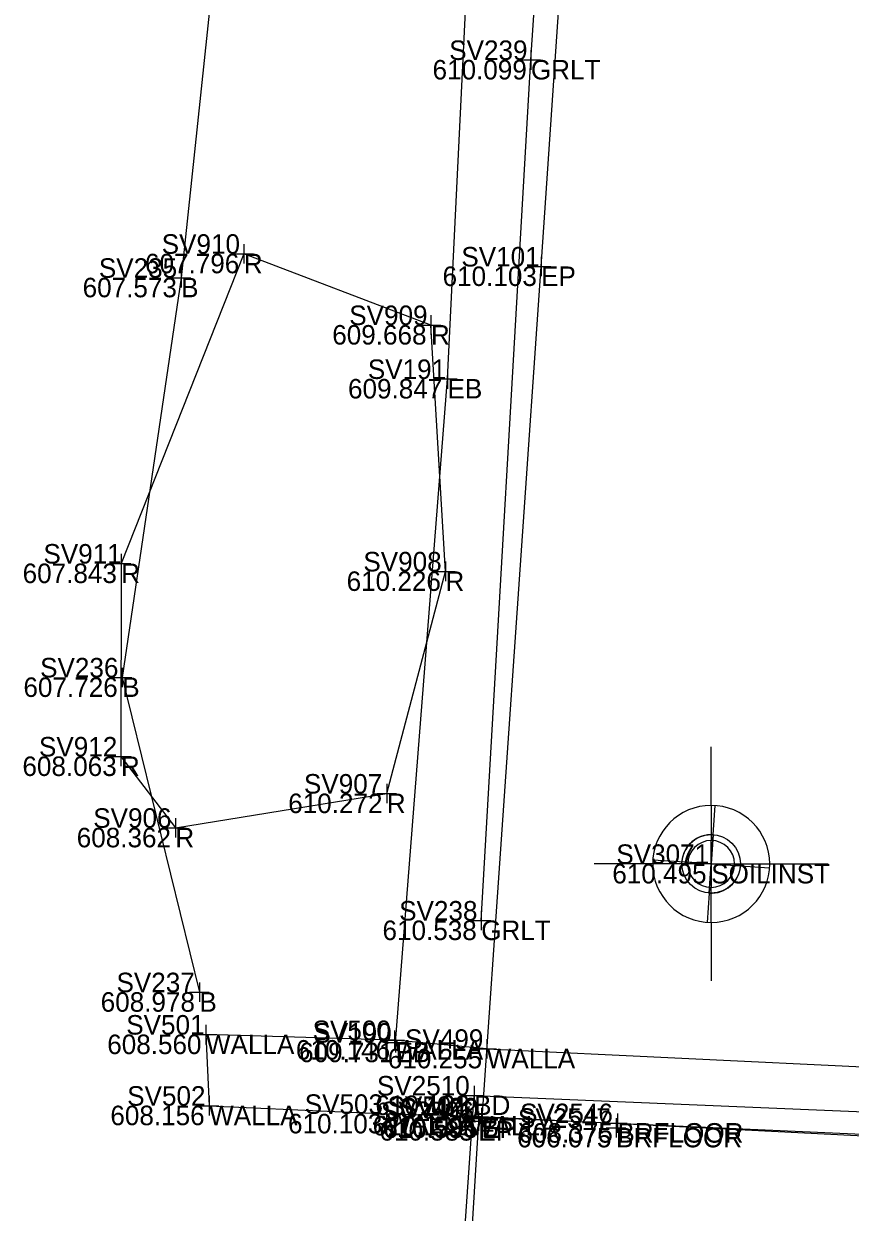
# Model space of a CAD drawing. Extents: x -2 to 1979875, y -2 to 232027.
# Drawn here: x 1978752.71 to 1978773.9, y 231291.3 to 231321.76 of the extents above; entities that cross this region are included whole.
import ezdxf

# ---------------------------------------------------------------- set-up
doc = ezdxf.new("R2010")
doc.units = 0
for name, color, linetype in [('_CIVIL_CONSTRUCTION', 7, 'Continuous'), ('BR_X_SV_Abut', 7, 'Continuous'), ('BR_X_SV_Deck_Floor_Text', 7, 'Continuous'), ('BR_X_SV_Deck_Top', 7, 'Continuous'), ('BR_X_SV_Deck_Top_Text', 7, 'Continuous'), ('DR_X_Erosion_Control', 7, 'Continuous'), ('GE_P_Alignment', 7, 'Continuous'), ('GE_P_Alignment_100_Curve_Data', 7, 'Continuous'), ('GE_P_Alignment_500_Stations', 7, 'Continuous'), ('GE_X_Alignment', 7, 'Continuous'), ('GE_X_Alignment_1000_Stations', 7, 'Continuous'), ('GE_X_Alignment_100_Curve_Data', 7, 'Continuous'), ('GE_X_Alignment_100_Stations', 7, 'Continuous'), ('GT_Project_Soil_Boring', 7, 'Continuous'), ('SC_Scratch1', 7, 'Continuous')]:
    doc.layers.add(name, color=color, linetype=linetype)

msp = doc.modelspace()

# ---------------------------------------------------------------- linework, layer by layer
at = {"layer": 'BR_X_SV_Abut'}
for p, q in [((1978764.58, 231295.485), (1978788.479, 231294.331)), ((1978764.125, 231293.766), (1978788.351, 231292.541))]:
    msp.add_line(p, q, dxfattribs=at)
msp.add_lwpolyline([(1978764.58, 231295.485), (1978762.22, 231295.709), (1978757.382, 231295.85), (1978757.464, 231294.028), (1978762.012, 231293.818), (1978764.125, 231293.766)], dxfattribs=at)
at = {"layer": 'BR_X_SV_Deck_Top'}
msp.add_lwpolyline([(1978761.339, 231252.043), (1978764.257, 231294.289), (1978788.348, 231293.277), (1978785.624, 231251.227)], close=True, dxfattribs=at)
at = {"layer": 'DR_X_Erosion_Control'}
msp.add_lwpolyline([(1978756.598, 231301.15), (1978762.019, 231302.027), (1978763.521, 231307.721), (1978763.15, 231314.035), (1978758.352, 231315.862), (1978755.208, 231307.922), (1978755.203, 231302.978)], close=True, dxfattribs=at)
at = {"layer": 'GE_P_Alignment'}
for points in [[(1978861.689, 231782.415), (1978851.853, 231763.969), (1978841.987, 231745.294), (1978832.802, 231726.204), (1978823.63, 231707.125), (1978815.734, 231686.751), (1978809.08, 231664.461), (1978799.472, 231640.53), (1978791.914, 231616.771), (1978786.956, 231593.117), (1978782.497, 231568.131), (1978778.452, 231542.695), (1978775.331, 231517.531), (1978773.11, 231494.147), (1978771.443, 231473.021), (1978766.839, 231446.726), (1978765.415, 231421.944), (1978763.995, 231399.725), (1978762.317, 231376.717), (1978760.52, 231353.776), (1978758.484, 231331.627), (1978756.746, 231315.247), (1978755.236, 231305.004), (1978757.214, 231296.936)], [(1978787.716, 231292.624), (1978776.886, 231293.168), (1978764.446, 231293.727)]]:
    msp.add_lwpolyline(points, dxfattribs=at)
at = {"layer": 'GE_P_Alignment_100_Curve_Data'}
msp.add_lwpolyline([(1978764.438, 231298.773), (1978765.712, 231320.829), (1978767.378, 231345.616), (1978768.807, 231367.39), (1978770.554, 231391.673), (1978771.722, 231416.416), (1978771.842, 231435.288), (1978771.576, 231449.202)], dxfattribs=at)
at = {"layer": 'GE_X_Alignment_1000_Stations'}
for points in [[(1978764.463, 231293.7), (1978765.973, 231315.536), (1978767.501, 231337.797), (1978768.95, 231360.619), (1978770.673, 231383.826), (1978772.372, 231407.034), (1978773.964, 231429.759), (1978775.312, 231448.487), (1978777.194, 231472.049), (1978779.086, 231494.381), (1978781.387, 231516.708), (1978784.451, 231540.773), (1978787.814, 231562.2), (1978793.416, 231590.474), (1978799.132, 231614.141), (1978805.307, 231636.271), (1978811.99, 231656.714), (1978821.006, 231681.034), (1978832.082, 231707.98), (1978843.434, 231732.641), (1978854.786, 231756.844), (1978866.633, 231780.181)], [(1978764.365, 231293.633), (1978762.994, 231271.213), (1978761.795, 231253.289)]]:
    msp.add_lwpolyline(points, dxfattribs=at)
at = {"layer": 'GE_X_Alignment_100_Curve_Data'}
for p, q in [((1978765.712, 231321.079), (1978765.712, 231320.579)), ((1978765.462, 231320.829), (1978765.962, 231320.829)), ((1978765.712, 231320.829), (1978765.712, 231320.829)), ((1978758.102, 231315.862), (1978758.602, 231315.862)), ((1978758.352, 231316.112), (1978758.352, 231315.612)), ((1978758.352, 231315.862), (1978758.352, 231315.862)), ((1978765.723, 231315.536), (1978766.223, 231315.536)), ((1978765.973, 231315.786), (1978765.973, 231315.286)), ((1978765.973, 231315.536), (1978765.973, 231315.536)), ((1978756.496, 231315.247), (1978756.996, 231315.247)), ((1978756.746, 231315.497), (1978756.746, 231314.997)), ((1978756.746, 231315.247), (1978756.746, 231315.247)), ((1978762.9, 231314.035), (1978763.4, 231314.035)), ((1978763.15, 231314.285), (1978763.15, 231313.785)), ((1978763.15, 231314.035), (1978763.15, 231314.035)), ((1978763.575, 231312.903), (1978763.575, 231312.403)), ((1978763.325, 231312.653), (1978763.825, 231312.653)), ((1978763.575, 231312.653), (1978763.575, 231312.653)), ((1978754.958, 231307.922), (1978755.458, 231307.922)), ((1978755.208, 231308.172), (1978755.208, 231307.672)), ((1978755.208, 231307.922), (1978755.208, 231307.922)), ((1978763.521, 231307.971), (1978763.521, 231307.471)), ((1978763.271, 231307.721), (1978763.771, 231307.721)), ((1978763.521, 231307.721), (1978763.521, 231307.721)), ((1978755.236, 231305.254), (1978755.236, 231304.754)), ((1978754.986, 231305.004), (1978755.486, 231305.004)), ((1978755.236, 231305.004), (1978755.236, 231305.004)), ((1978755.203, 231303.228), (1978755.203, 231302.728)), ((1978754.953, 231302.978), (1978755.453, 231302.978)), ((1978755.203, 231302.978), (1978755.203, 231302.978)), ((1978762.019, 231302.277), (1978762.019, 231301.777)), ((1978761.769, 231302.027), (1978762.269, 231302.027)), ((1978762.019, 231302.027), (1978762.019, 231302.027)), ((1978756.598, 231301.4), (1978756.598, 231300.9)), ((1978756.348, 231301.15), (1978756.848, 231301.15)), ((1978756.598, 231301.15), (1978756.598, 231301.15)), ((1978764.438, 231299.023), (1978764.438, 231298.523)), ((1978764.188, 231298.773), (1978764.688, 231298.773)), ((1978764.438, 231298.773), (1978764.438, 231298.773)), ((1978757.214, 231297.186), (1978757.214, 231296.686)), ((1978756.964, 231296.936), (1978757.464, 231296.936)), ((1978757.214, 231296.936), (1978757.214, 231296.936)), ((1978757.382, 231296.1), (1978757.382, 231295.6)), ((1978757.132, 231295.85), (1978757.632, 231295.85)), ((1978757.382, 231295.85), (1978757.382, 231295.85)), ((1978762.22, 231295.959), (1978762.22, 231295.459)), ((1978762.241, 231295.893), (1978762.241, 231295.393)), ((1978761.97, 231295.709), (1978762.47, 231295.709)), ((1978761.991, 231295.643), (1978762.491, 231295.643)), ((1978762.22, 231295.709), (1978762.22, 231295.709)), ((1978762.241, 231295.643), (1978762.241, 231295.643)), ((1978764.33, 231295.485), (1978764.83, 231295.485)), ((1978764.58, 231295.735), (1978764.58, 231295.235)), ((1978764.58, 231295.485), (1978764.58, 231295.485)), ((1978764.257, 231294.539), (1978764.257, 231294.039)), ((1978757.464, 231294.278), (1978757.464, 231293.778)), ((1978764.007, 231294.289), (1978764.507, 231294.289)), ((1978764.257, 231294.289), (1978764.257, 231294.289)), ((1978757.214, 231294.028), (1978757.714, 231294.028)), ((1978757.464, 231294.028), (1978757.464, 231294.028)), ((1978762.012, 231294.068), (1978762.012, 231293.568)), ((1978764.125, 231294.016), (1978764.125, 231293.516)), ((1978764.446, 231293.977), (1978764.446, 231293.477)), ((1978764.463, 231293.95), (1978764.463, 231293.45)), ((1978761.762, 231293.818), (1978762.262, 231293.818)), ((1978762.012, 231293.818), (1978762.012, 231293.818)), ((1978763.875, 231293.766), (1978764.375, 231293.766)), ((1978764.115, 231293.633), (1978764.615, 231293.633)), ((1978764.125, 231293.766), (1978764.125, 231293.766)), ((1978764.196, 231293.727), (1978764.696, 231293.727)), ((1978764.213, 231293.7), (1978764.713, 231293.7)), ((1978764.365, 231293.883), (1978764.365, 231293.383)), ((1978764.365, 231293.633), (1978764.365, 231293.633)), ((1978764.446, 231293.727), (1978764.446, 231293.727)), ((1978764.463, 231293.7), (1978764.463, 231293.7)), ((1978767.894, 231293.71), (1978767.894, 231293.21)), ((1978767.929, 231293.831), (1978767.929, 231293.331)), ((1978767.644, 231293.46), (1978768.144, 231293.46)), ((1978767.679, 231293.581), (1978768.179, 231293.581)), ((1978767.894, 231293.46), (1978767.894, 231293.46)), ((1978767.929, 231293.581), (1978767.929, 231293.581))]:
    msp.add_line(p, q, dxfattribs=at)
at = {"layer": 'GT_Project_Soil_Boring'}
for p, q in [((1978770.334, 231300.224), (1978770.434, 231301.721)), ((1978770.384, 231300.972), (1978770.334, 231300.224)), ((1978770.334, 231300.224), (1978768.837, 231300.324)), ((1978770.334, 231300.224), (1978769.586, 231300.274)), ((1978770.334, 231300.224), (1978770.234, 231298.727)), ((1978770.284, 231299.476), (1978770.334, 231300.224)), ((1978770.334, 231300.224), (1978771.831, 231300.124)), ((1978770.334, 231300.224), (1978771.082, 231300.174))]:
    msp.add_line(p, q, dxfattribs=at)
msp.add_circle((1978770.334, 231300.224), 0.75, dxfattribs=at)
for start, end in [(86.1708, 176.1708), (266.1708, 356.1708)]:
    msp.add_arc((1978770.334, 231300.224), 0.75, start, end, dxfattribs=at)
at = {"layer": 'SC_Scratch1'}
for p, q in [((1978770.334, 231301.724), (1978770.334, 231303.224)), ((1978770.334, 231301.724), (1978770.334, 231300.824)), ((1978770.334, 231300.224), (1978770.334, 231300.824)), ((1978768.834, 231300.224), (1978767.334, 231300.224)), ((1978769.734, 231300.224), (1978768.834, 231300.224)), ((1978770.334, 231300.224), (1978769.734, 231300.224)), ((1978770.334, 231300.224), (1978770.934, 231300.224)), ((1978770.334, 231300.224), (1978770.334, 231299.624)), ((1978770.934, 231300.224), (1978771.834, 231300.224)), ((1978771.834, 231300.224), (1978773.334, 231300.224)), ((1978770.334, 231298.724), (1978770.334, 231299.624)), ((1978770.334, 231298.724), (1978770.334, 231297.224))]:
    msp.add_line(p, q, dxfattribs=at)
msp.add_lwpolyline([(1978762.241, 231295.643), (1978763.575, 231312.653), (1978764.638, 231334.283), (1978765.818, 231356.042), (1978767.705, 231380.515), (1978769.009, 231402.257), (1978769.844, 231423.935), (1978772.522, 231443.246), (1978774.792, 231466.077), (1978776.974, 231489.898), (1978779.234, 231514.617), (1978782.489, 231539.582), (1978786.101, 231563.808), (1978790.249, 231586.35), (1978795.964, 231611.211), (1978802.838, 231634.974), (1978810.373, 231657.227), (1978818.1, 231678.589), (1978826.474, 231699.286), (1978835.162, 231719.41), (1978844.319, 231739.683), (1978854.914, 231761.571), (1978865.037, 231781.151)], dxfattribs=at)
for radius, start, end in [(1.5, 90, 180), (1.5, 0, 90), (0.6, 90, 180), (0.6, 0, 90), (1.5, 180, 270), (0.6, 180, 270), (0.6, 270, 0), (1.5, 270, 0)]:
    msp.add_arc((1978770.334, 231300.224), radius, start, end, dxfattribs=at)

# ---------------------------------------------------------------- texts
at = {"layer": '_CIVIL_CONSTRUCTION'}
for s, p in [('610.099', (1978763.191, 231320.329)), ('607.796', (1978755.82, 231315.362)), ('610.103', (1978763.448, 231315.036)), ('607.573', (1978754.221, 231314.747)), ('609.668', (1978760.62, 231313.535)), ('609.847', (1978761.024, 231312.153)), ('607.843', (1978752.683, 231307.422)), ('610.226', (1978760.989, 231307.221)), ('607.726', (1978752.704, 231304.504)), ('608.063', (1978752.678, 231302.478)), ('610.272', (1978759.491, 231301.527)), ('608.362', (1978754.07, 231300.65)), ('610.495', (1978767.799, 231299.724)), ('610.538', (1978761.908, 231298.273)), ('608.978', (1978754.684, 231296.436)), ('609.731', (1978759.771, 231295.143)), ('610.585', (1978761.83, 231293.133)), ('610.595', (1978761.911, 231293.227)), ('610.586', (1978761.931, 231293.2))]:
    msp.add_text(s, height=0.5, dxfattribs=at).set_placement(p)
at = {"layer": 'BR_X_SV_Deck_Floor_Text'}
for s, p in [('SV2547', (1978765.381, 231293.46)), ('SV2546', (1978765.435, 231293.581)), ('606.075', (1978765.359, 231292.96)), ('608.375', (1978765.394, 231293.081)), ('BRFLOOR', (1978767.894, 231292.96)), ('BRFLOOR', (1978767.929, 231293.081))]:
    msp.add_text(s, height=0.5, dxfattribs=at).set_placement(p)
at = {"layer": 'BR_X_SV_Deck_Top_Text'}
for s, p in [('SV2510', (1978761.765, 231294.289)), ('610.138', (1978761.727, 231293.789)), ('BD', (1978764.257, 231293.789))]:
    msp.add_text(s, height=0.5, dxfattribs=at).set_placement(p)
at = {"layer": 'GE_P_Alignment_500_Stations'}
for s, p in [('SV501', (1978755.339, 231295.85)), ('SV500', (1978760.116, 231295.709)), ('608.560', (1978754.852, 231295.35)), ('WALLA', (1978757.382, 231295.35)), ('SV499', (1978762.486, 231295.485)), ('610.146', (1978759.688, 231295.209)), ('610.255', (1978762.045, 231294.985)), ('WALLA', (1978762.22, 231295.209)), ('WALLA', (1978764.58, 231294.985)), ('SV502', (1978755.363, 231294.028)), ('SV503', (1978759.914, 231293.818)), ('SV504', (1978762.036, 231293.766)), ('608.156', (1978754.932, 231293.528)), ('WALLA', (1978757.464, 231293.528)), ('610.103', (1978759.487, 231293.318)), ('610.121', (1978761.655, 231293.266)), ('WALLA', (1978762.012, 231293.318)), ('WALLA', (1978764.125, 231293.266))]:
    msp.add_text(s, height=0.5, dxfattribs=at).set_placement(p)
at = {"layer": 'GE_X_Alignment'}
for s, p in [('SV239', (1978763.618, 231320.829)), ('SV910', (1978756.248, 231315.862)), ('SV101', (1978763.93, 231315.536)), ('SV235', (1978754.637, 231315.247)), ('SV909', (1978761.056, 231314.035)), ('SV191', (1978761.532, 231312.653)), ('SV911', (1978753.216, 231307.922)), ('SV908', (1978761.418, 231307.721)), ('SV236', (1978753.131, 231305.004)), ('SV912', (1978753.102, 231302.978)), ('SV907', (1978759.894, 231302.027)), ('SV906', (1978754.493, 231301.15)), ('SV3071', (1978767.902, 231300.224)), ('SV238', (1978762.335, 231298.773)), ('SV237', (1978755.089, 231296.936)), ('SV190', (1978760.137, 231295.643)), ('SV422', (1978762.345, 231293.727)), ('SV2506', (1978761.871, 231293.633)), ('SV100', (1978762.359, 231293.7))]:
    msp.add_text(s, height=0.5, dxfattribs=at).set_placement(p)
at = {"layer": 'GE_X_Alignment_100_Stations'}
for s, p in [('GRLT', (1978765.712, 231320.329)), ('R', (1978758.352, 231315.362)), ('EP', (1978765.973, 231315.036)), ('B', (1978756.746, 231314.747)), ('R', (1978763.15, 231313.535)), ('EB', (1978763.575, 231312.153)), ('R', (1978755.208, 231307.422)), ('R', (1978763.521, 231307.221)), ('B', (1978755.236, 231304.504)), ('R', (1978755.203, 231302.478)), ('R', (1978762.019, 231301.527)), ('R', (1978756.598, 231300.65)), ('SOILINST', (1978770.334, 231299.724)), ('GRLT', (1978764.438, 231298.273)), ('B', (1978757.214, 231296.436)), ('EB', (1978762.241, 231295.143)), ('EP', (1978764.365, 231293.133)), ('B', (1978764.446, 231293.227)), ('EP', (1978764.463, 231293.2))]:
    msp.add_text(s, height=0.5, dxfattribs=at).set_placement(p)

doc.saveas('drawing.dxf')
